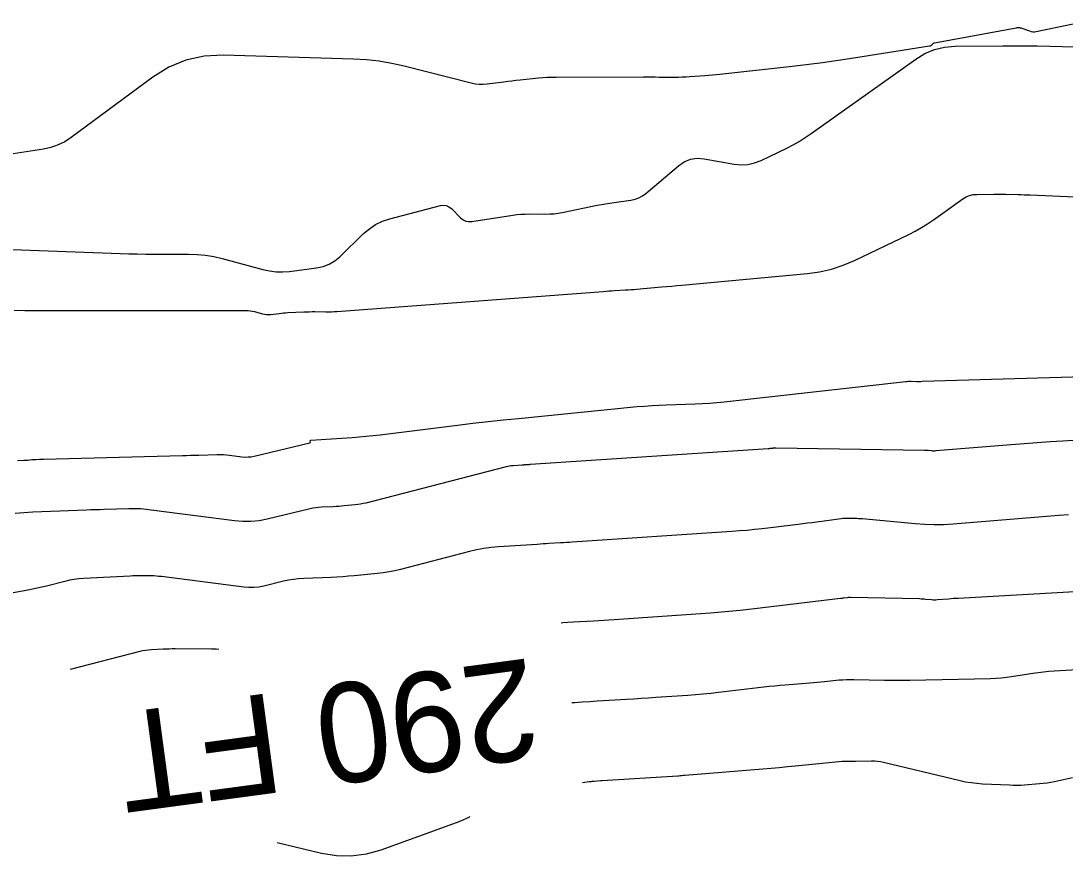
# Model space of a CAD drawing. Extents: x 1768942 to 1774819, y 723037 to 732099.
# Drawn here: x 1769088.8 to 1769151.7, y 731868.5 to 731918.8 of the extents above; entities that cross this region are included whole.
import ezdxf

# ---------------------------------------------------------------- set-up
doc = ezdxf.new("R2010")
doc.units = 0
doc.layers.add('R_Contour Annot', color=7, linetype='Continuous')
doc.layers.add('R_Contours', color=7, linetype='Continuous')

msp = doc.modelspace()

# ---------------------------------------------------------------- linework, layer by layer
at = {"layer": 'R_Contours'}
for points in [[(1769153.107, 731918.774), (1769149.906, 731918.118), (1769149.81, 731918.105), (1769149.715, 731918.105), (1769149.62, 731918.119), (1769149.527, 731918.146), (1769149.017, 731918.332), (1769148.992, 731918.34), (1769148.968, 731918.346), (1769148.943, 731918.349), (1769148.918, 731918.351), (1769148.816, 731918.353), (1769148.79, 731918.353), (1769148.765, 731918.352), (1769148.74, 731918.349), (1769148.715, 731918.345), (1769143.79, 731917.441), (1769143.761, 731917.433), (1769143.734, 731917.421), (1769143.709, 731917.406), (1769143.686, 731917.386), (1769143.599, 731917.299), (1769143.576, 731917.279), (1769143.551, 731917.264), (1769143.524, 731917.252), (1769143.495, 731917.245), (1769138.678, 731916.49), (1769137.864, 731916.367), (1769137.05, 731916.254), (1769136.234, 731916.15), (1769135.416, 731916.055), (1769130.88, 731915.558), (1769130.654, 731915.534), (1769130.428, 731915.512), (1769130.202, 731915.492), (1769129.975, 731915.474), (1769129.069, 731915.406), (1769128.843, 731915.391), (1769128.616, 731915.381), (1769128.389, 731915.375), (1769128.162, 731915.374), (1769127.218, 731915.378), (1769126.985, 731915.379), (1769126.752, 731915.38), (1769126.519, 731915.38), (1769126.286, 731915.38), (1769121.023, 731915.372), (1769120.756, 731915.369), (1769120.49, 731915.359), (1769120.224, 731915.342), (1769119.958, 731915.319), (1769118.857, 731915.209), (1769118.61, 731915.183), (1769118.364, 731915.155), (1769118.117, 731915.126), (1769117.871, 731915.094), (1769116.886, 731914.964), (1769116.641, 731914.943), (1769116.396, 731914.946), (1769116.154, 731914.972), (1769115.912, 731915.022), (1769111.891, 731916.049), (1769111.138, 731916.22), (1769110.378, 731916.348), (1769109.613, 731916.434), (1769108.842, 731916.477), (1769100.981, 731916.705), (1769099.839, 731916.648), (1769098.753, 731916.408), (1769097.725, 731915.986), (1769096.754, 731915.381), (1769091.844, 731911.756), (1769091.461, 731911.507), (1769091.056, 731911.309), (1769090.631, 731911.162), (1769090.184, 731911.066), (1769088.354, 731910.785)], [(1769086.118, 731905.109), (1769094.794, 731904.782), (1769095.308, 731904.765), (1769095.822, 731904.752), (1769096.337, 731904.745), (1769096.851, 731904.743), (1769098.909, 731904.742), (1769099.421, 731904.726), (1769099.929, 731904.676), (1769100.433, 731904.592), (1769100.932, 731904.476), (1769103.378, 731903.82), (1769103.776, 731903.734), (1769104.177, 731903.686), (1769104.58, 731903.678), (1769104.986, 731903.709), (1769106.616, 731903.913), (1769107.01, 731903.993), (1769107.374, 731904.133), (1769107.711, 731904.331), (1769108.019, 731904.589), (1769109.437, 731905.975), (1769109.786, 731906.275), (1769110.164, 731906.524), (1769110.572, 731906.72), (1769111.01, 731906.865), (1769114.063, 731907.663), (1769114.247, 731907.689), (1769114.418, 731907.668), (1769114.577, 731907.599), (1769114.722, 731907.483), (1769115.279, 731906.925), (1769115.425, 731906.807), (1769115.585, 731906.731), (1769115.759, 731906.698), (1769115.947, 731906.707), (1769118.415, 731907.088), (1769118.662, 731907.121), (1769118.91, 731907.144), (1769119.158, 731907.157), (1769119.408, 731907.161), (1769120.406, 731907.153), (1769120.655, 731907.158), (1769120.903, 731907.176), (1769121.15, 731907.207), (1769121.395, 731907.25), (1769123.503, 731907.683), (1769123.754, 731907.732), (1769124.006, 731907.777), (1769124.259, 731907.818), (1769124.513, 731907.854), (1769125.528, 731907.992), (1769125.775, 731908.043), (1769126.006, 731908.127), (1769126.224, 731908.243), (1769126.426, 731908.393), (1769128.383, 731910.053), (1769128.736, 731910.297), (1769129.113, 731910.448), (1769129.516, 731910.508), (1769129.943, 731910.477), (1769131.737, 731910.162), (1769132.155, 731910.12), (1769132.564, 731910.143), (1769132.964, 731910.231), (1769133.355, 731910.384), (1769134.901, 731911.126), (1769135.283, 731911.319), (1769135.656, 731911.528), (1769136.019, 731911.753), (1769136.373, 731911.994), (1769142.672, 731916.476), (1769143.218, 731916.807), (1769143.794, 731917.046), (1769144.4, 731917.192), (1769145.036, 731917.246), (1769147.906, 731917.279), (1769148.424, 731917.283), (1769148.943, 731917.282), (1769149.461, 731917.276), (1769149.98, 731917.266), (1769152.998, 731917.194)], [(1769088.419, 731901.379), (1769089.059, 731901.363), (1769089.699, 731901.354), (1769090.34, 731901.351), (1769102.372, 731901.35), (1769102.498, 731901.345), (1769102.623, 731901.333), (1769102.747, 731901.313), (1769102.87, 731901.284), (1769103.36, 731901.153), (1769103.483, 731901.126), (1769103.607, 731901.111), (1769103.731, 731901.109), (1769103.857, 731901.118), (1769104.366, 731901.182), (1769104.492, 731901.197), (1769104.62, 731901.209), (1769104.747, 731901.218), (1769104.874, 731901.226), (1769105.844, 731901.271), (1769106.01, 731901.278), (1769106.176, 731901.282), (1769106.343, 731901.285), (1769106.509, 731901.284), (1769107.173, 731901.278), (1769107.34, 731901.279), (1769107.506, 731901.283), (1769107.671, 731901.29), (1769107.837, 731901.3), (1769123.863, 731902.503), (1769124.03, 731902.515), (1769124.197, 731902.527), (1769124.364, 731902.538), (1769124.531, 731902.548), (1769125.2, 731902.59), (1769125.367, 731902.601), (1769125.534, 731902.612), (1769125.701, 731902.625), (1769125.867, 731902.639), (1769127.37, 731902.768), (1769127.676, 731902.794), (1769127.982, 731902.821), (1769128.288, 731902.849), (1769128.594, 731902.877), (1769136.143, 731903.579), (1769136.879, 731903.68), (1769137.598, 731903.845), (1769138.298, 731904.073), (1769138.982, 731904.365), (1769142.24, 731905.928), (1769142.629, 731906.125), (1769143.009, 731906.338), (1769143.38, 731906.568), (1769143.741, 731906.813), (1769145.503, 731908.067), (1769145.696, 731908.184), (1769145.9, 731908.269), (1769146.114, 731908.321), (1769146.339, 731908.34), (1769147.354, 731908.351), (1769147.537, 731908.352), (1769147.72, 731908.352), (1769147.904, 731908.35), (1769148.087, 731908.347), (1769148.821, 731908.329), (1769149.004, 731908.324), (1769149.187, 731908.318), (1769149.371, 731908.311), (1769149.554, 731908.304), (1769158.513, 731907.904)], [(1769088.607, 731892.336), (1769088.994, 731892.345), (1769089.054, 731892.347), (1769089.114, 731892.35), (1769089.173, 731892.354), (1769089.233, 731892.359), (1769089.473, 731892.383), (1769089.533, 731892.388), (1769089.592, 731892.393), (1769089.652, 731892.396), (1769089.711, 731892.399), (1769089.949, 731892.409), (1769090.008, 731892.411), (1769090.068, 731892.413), (1769090.127, 731892.415), (1769090.187, 731892.416), (1769098.538, 731892.632), (1769098.784, 731892.639), (1769099.031, 731892.645), (1769099.277, 731892.652), (1769099.524, 731892.659), (1769100.628, 731892.689), (1769100.815, 731892.69), (1769101.002, 731892.685), (1769101.189, 731892.672), (1769101.375, 731892.652), (1769102.119, 731892.557), (1769102.305, 731892.541), (1769102.49, 731892.543), (1769102.674, 731892.561), (1769102.857, 731892.597), (1769106.211, 731893.4), (1769106.225, 731893.406), (1769106.236, 731893.415), (1769106.241, 731893.428), (1769106.242, 731893.443), (1769106.235, 731893.513), (1769106.236, 731893.529), (1769106.242, 731893.54), (1769106.252, 731893.547), (1769106.267, 731893.55), (1769108.756, 731893.719), (1769109.177, 731893.75), (1769109.596, 731893.787), (1769110.016, 731893.83), (1769110.434, 731893.879), (1769115.095, 731894.457), (1769116.011, 731894.567), (1769116.928, 731894.672), (1769117.846, 731894.771), (1769118.765, 731894.865), (1769125.909, 731895.569), (1769126.343, 731895.608), (1769126.777, 731895.64), (1769127.212, 731895.665), (1769127.647, 731895.682), (1769129.389, 731895.739), (1769129.825, 731895.757), (1769130.259, 731895.784), (1769130.693, 731895.819), (1769131.127, 731895.863), (1769142.075, 731897.081), (1769142.155, 731897.089), (1769142.236, 731897.094), (1769142.317, 731897.097), (1769142.398, 731897.097), (1769142.722, 731897.091), (1769142.803, 731897.09), (1769142.883, 731897.091), (1769142.964, 731897.092), (1769143.045, 731897.093), (1769158.37, 731897.545)], [(1769157.989, 731893.923), (1769151.522, 731893.499), (1769150.744, 731893.447), (1769149.967, 731893.392), (1769149.19, 731893.333), (1769148.413, 731893.271), (1769143.867, 731892.902), (1769143.81, 731892.898), (1769143.753, 731892.897), (1769143.696, 731892.899), (1769143.639, 731892.903), (1769143.412, 731892.924), (1769143.355, 731892.929), (1769143.298, 731892.933), (1769143.241, 731892.935), (1769143.184, 731892.937), (1769134.238, 731893.082), (1769134.22, 731893.082), (1769134.202, 731893.081), (1769134.185, 731893.079), (1769134.167, 731893.077), (1769134.097, 731893.068), (1769134.08, 731893.066), (1769134.062, 731893.064), (1769134.045, 731893.061), (1769134.027, 731893.059), (1769133.892, 731893.043), (1769133.864, 731893.04), (1769133.835, 731893.037), (1769133.807, 731893.035), (1769133.778, 731893.033), (1769119.478, 731892.085), (1769119.437, 731892.082), (1769119.395, 731892.079), (1769119.354, 731892.076), (1769119.312, 731892.074), (1769119.147, 731892.063), (1769119.105, 731892.061), (1769119.064, 731892.058), (1769119.022, 731892.055), (1769118.981, 731892.053), (1769118.431, 731892.017), (1769118.326, 731892.007), (1769118.222, 731891.993), (1769118.119, 731891.974), (1769118.016, 731891.95), (1769109.582, 731889.773), (1769109.422, 731889.735), (1769109.26, 731889.703), (1769109.098, 731889.678), (1769108.934, 731889.659), (1769108.277, 731889.595), (1769108.113, 731889.58), (1769107.948, 731889.568), (1769107.784, 731889.557), (1769107.619, 731889.549), (1769106.904, 731889.519), (1769106.73, 731889.508), (1769106.558, 731889.488), (1769106.387, 731889.46), (1769106.217, 731889.423), (1769103.637, 731888.805), (1769103.149, 731888.711), (1769102.659, 731888.662), (1769102.167, 731888.658), (1769101.672, 731888.699), (1769096.027, 731889.42), (1769095.968, 731889.426), (1769095.91, 731889.43), (1769095.851, 731889.432), (1769095.792, 731889.431), (1769095.557, 731889.425), (1769095.498, 731889.423), (1769095.439, 731889.422), (1769095.38, 731889.42), (1769095.322, 731889.419), (1769093.834, 731889.38), (1769093.567, 731889.373), (1769093.3, 731889.365), (1769093.032, 731889.355), (1769092.765, 731889.345), (1769090.077, 731889.24), (1769089.541, 731889.215), (1769089.005, 731889.182), (1769088.469, 731889.141)], [(1769151.863, 731889.067), (1769151.279, 731889.021), (1769144.911, 731888.503), (1769144.342, 731888.469), (1769143.773, 731888.46), (1769143.204, 731888.476), (1769142.636, 731888.517), (1769139.434, 731888.815), (1769139.329, 731888.824), (1769139.224, 731888.831), (1769139.119, 731888.836), (1769139.014, 731888.838), (1769138.593, 731888.845), (1769138.488, 731888.845), (1769138.383, 731888.841), (1769138.278, 731888.833), (1769138.174, 731888.821), (1769136.705, 731888.625), (1769136.426, 731888.588), (1769136.146, 731888.553), (1769135.866, 731888.518), (1769135.586, 731888.484), (1769133.422, 731888.226), (1769132.968, 731888.174), (1769132.513, 731888.129), (1769132.058, 731888.09), (1769131.602, 731888.057), (1769121.996, 731887.42), (1769121.821, 731887.408), (1769121.646, 731887.397), (1769121.47, 731887.386), (1769121.295, 731887.375), (1769120.594, 731887.33), (1769120.418, 731887.319), (1769120.243, 731887.308), (1769120.068, 731887.297), (1769119.893, 731887.285), (1769117.567, 731887.132), (1769117.123, 731887.093), (1769116.682, 731887.032), (1769116.244, 731886.952), (1769115.81, 731886.85), (1769111.654, 731885.778), (1769111.313, 731885.697), (1769110.97, 731885.629), (1769110.625, 731885.575), (1769110.277, 731885.535), (1769108.881, 731885.399), (1769108.532, 731885.368), (1769108.183, 731885.341), (1769107.833, 731885.319), (1769107.483, 731885.302), (1769105.836, 731885.232), (1769105.53, 731885.212), (1769105.227, 731885.177), (1769104.926, 731885.128), (1769104.626, 731885.064), (1769103.433, 731884.778), (1769103.134, 731884.72), (1769102.833, 731884.69), (1769102.531, 731884.687), (1769102.228, 731884.712), (1769097.283, 731885.344), (1769097.126, 731885.362), (1769096.97, 731885.375), (1769096.813, 731885.383), (1769096.655, 731885.386), (1769096.025, 731885.39), (1769095.867, 731885.39), (1769095.71, 731885.388), (1769095.552, 731885.383), (1769095.395, 731885.376), (1769092.59, 731885.231), (1769092.306, 731885.209), (1769092.024, 731885.173), (1769091.744, 731885.124), (1769091.467, 731885.06), (1769090.361, 731884.777), (1769090.084, 731884.709), (1769089.806, 731884.645), (1769089.526, 731884.587), (1769089.246, 731884.533), (1769087.028, 731884.129)], [(1769154.691, 731884.562), (1769145.214, 731884.037), (1769145.072, 731884.029), (1769144.93, 731884.02), (1769144.788, 731884.009), (1769144.645, 731883.998), (1769143.971, 731883.944), (1769143.882, 731883.938), (1769143.793, 731883.937), (1769143.703, 731883.939), (1769143.614, 731883.946), (1769143.257, 731883.979), (1769143.168, 731883.986), (1769143.078, 731883.992), (1769142.989, 731883.997), (1769142.899, 731884), (1769138.743, 731884.09), (1769138.691, 731884.09), (1769138.64, 731884.088), (1769138.589, 731884.085), (1769138.537, 731884.079), (1769138.332, 731884.051), (1769138.281, 731884.045), (1769138.23, 731884.038), (1769138.178, 731884.032), (1769138.127, 731884.026), (1769132.953, 731883.408), (1769132.072, 731883.309), (1769131.191, 731883.221), (1769130.309, 731883.145), (1769129.426, 731883.081), (1769124.514, 731882.755), (1769124.205, 731882.735), (1769123.896, 731882.715), (1769123.587, 731882.695), (1769123.278, 731882.675), (1769122.041, 731882.597), (1769121.732, 731882.578), (1769121.423, 731882.558), (1769121.322, 731882.551)], [(1769100.722, 731880.964), (1769100.569, 731880.972), (1769100.296, 731880.978), (1769098.102, 731880.993), (1769097.923, 731880.993), (1769097.745, 731880.99), (1769097.566, 731880.985), (1769097.388, 731880.977), (1769096.675, 731880.94), (1769096.497, 731880.926), (1769096.321, 731880.904), (1769096.146, 731880.873), (1769095.972, 731880.833), (1769091.788, 731879.762)], [(1769121.966, 731877.767), (1769122.159, 731877.779), (1769122.602, 731877.808), (1769123.045, 731877.836), (1769123.488, 731877.864), (1769125.26, 731877.976), (1769125.703, 731878.004), (1769126.146, 731878.032), (1769126.589, 731878.061), (1769127.032, 731878.09), (1769128.941, 731878.217), (1769129.406, 731878.251), (1769129.871, 731878.291), (1769130.336, 731878.337), (1769130.8, 731878.389), (1769133.516, 731878.714), (1769133.837, 731878.75), (1769134.158, 731878.784), (1769134.48, 731878.815), (1769134.802, 731878.843), (1769136.293, 731878.965), (1769136.514, 731878.983), (1769136.735, 731879.002), (1769136.956, 731879.022), (1769137.176, 731879.043), (1769138.059, 731879.129), (1769138.28, 731879.147), (1769138.501, 731879.158), (1769138.722, 731879.163), (1769138.943, 731879.162), (1769140.787, 731879.12), (1769141.169, 731879.114), (1769141.55, 731879.111), (1769141.931, 731879.113), (1769142.312, 731879.119), (1769147.155, 731879.218), (1769147.476, 731879.23), (1769147.797, 731879.254), (1769148.117, 731879.288), (1769148.436, 731879.334), (1769149.709, 731879.54), (1769150.028, 731879.587), (1769150.348, 731879.626), (1769150.668, 731879.656), (1769150.99, 731879.678), (1769153.084, 731879.794)], [(1769152.099, 731873.241), (1769151.012, 731873.003), (1769150.789, 731872.958), (1769150.565, 731872.921), (1769150.34, 731872.892), (1769150.114, 731872.872), (1769149.206, 731872.804), (1769148.979, 731872.791), (1769148.751, 731872.785), (1769148.524, 731872.785), (1769148.297, 731872.793), (1769146.689, 731872.87), (1769146.347, 731872.894), (1769146.006, 731872.935), (1769145.668, 731872.991), (1769145.332, 731873.062), (1769140.724, 731874.161), (1769140.545, 731874.197), (1769140.365, 731874.223), (1769140.184, 731874.236), (1769140.002, 731874.238), (1769139.038, 731874.218), (1769138.972, 731874.217), (1769138.905, 731874.217), (1769138.838, 731874.217), (1769138.772, 731874.219), (1769138.505, 731874.225), (1769138.438, 731874.225), (1769138.371, 731874.224), (1769138.305, 731874.22), (1769138.239, 731874.215), (1769135.432, 731873.943), (1769134.942, 731873.897), (1769134.452, 731873.852), (1769133.962, 731873.809), (1769133.471, 731873.768), (1769128.775, 731873.384), (1769128.752, 731873.382), (1769128.73, 731873.38), (1769128.708, 731873.378), (1769128.685, 731873.375), (1769128.59, 731873.364), (1769128.571, 731873.362), (1769128.552, 731873.36), (1769128.532, 731873.358), (1769128.513, 731873.357), (1769128.416, 731873.35), (1769128.358, 731873.347), (1769123.795, 731873.059), (1769123.768, 731873.058), (1769123.721, 731873.055), (1769123.715, 731873.054), (1769123.315, 731873.026), (1769123.246, 731873.02), (1769123.177, 731873.014), (1769123.108, 731873.007), (1769123.04, 731872.999), (1769122.614, 731872.948)], [(1769115.829, 731870.888), (1769115.722, 731870.833), (1769115.366, 731870.673), (1769115.002, 731870.531), (1769110.47, 731868.9), (1769109.588, 731868.651), (1769108.699, 731868.534), (1769107.802, 731868.55), (1769106.898, 731868.699), (1769104.245, 731869.33)]]:
    msp.add_lwpolyline(points, dxfattribs=at)

# ---------------------------------------------------------------- texts
at = {"layer": 'R_Contour Annot'}
msp.add_text('290 FT', height=6, rotation=187.66091, dxfattribs=at).set_placement((1769119.482, 731880.461))

doc.saveas('drawing.dxf')
